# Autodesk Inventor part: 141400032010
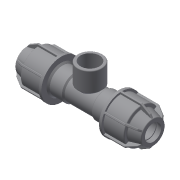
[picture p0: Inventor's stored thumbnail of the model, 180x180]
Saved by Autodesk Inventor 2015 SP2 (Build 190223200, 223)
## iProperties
Created: 2017-08
Part Number: 141400032010
Material: Generic
Description: PLASSON L.14 TEE FEMALE ADAPTOR (SILVER) 32 x 1" x 32
Document SubType Name: Modeling
Designer: KIM
Density: 1 g/cm^3
Appearance: Default
Author: KIM
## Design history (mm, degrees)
derived "141400.ipt"
feature "Solid1::141400.ipt"
feature "Solid2::141400.ipt"
tag "TaggingFeature1"
body "Solid1"
other parameters: "d1" = 32, "d2" = 56, "d4" = 15 deg, "d5" = 36.96, "d6" = 12.1968, "d10" = 61, "d16" = 32.64, "d17" = 2.8, "d22" = 51.2, "d24" = 2.8, "d25" = 54.9, "d26" = 45.75, "d27" = 2.8, "d28" = 135 deg, "d29" = 1.68, "d31" = 1.6, "d46" = 150 deg, "d49" = 3.05, "d50" = 0, "d58" = 0.96, "d61" = 360 deg, "d63" = 28.8, "d64" = 75, "d80" = 46.08, "d81" = 2.56, "d84" = 2.8, "d94" = 55, "d95" = 30.291, "d96" = 39.3783, "d97" = 21, "d98" = 25.6, "d99" = 35.44047, "d100" = 135 deg, "d108" = 1.6, "d111" = 0, "d_" = 32, "G_" = 30.291, "E_" = 61, "l_" = 56, "l_2" = 21, "A_" = 55
